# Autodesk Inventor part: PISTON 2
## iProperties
Created: 2004-11
Part Number: PISTON 2
Document SubType Name: Modeling
Designer: Bruno
Manufacturer: Standard
Standards Organization: Custom
Author: Bruno
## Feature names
1. Base1
